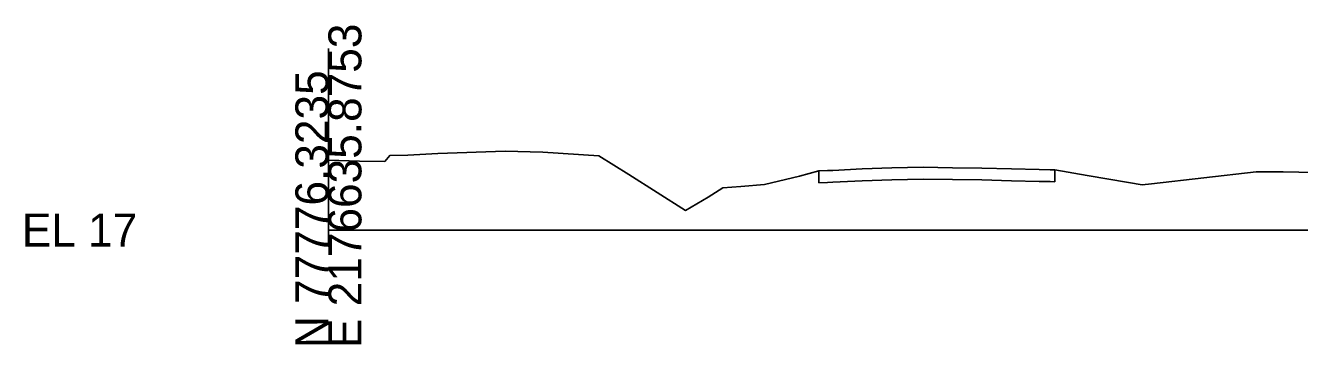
# Model space of a CAD drawing. Extents: x 2177029 to 2201446, y 59897 to 78390.
# Drawn here: x 2200017 to 2200125.1, y 66897.6 to 66924.6 of the extents above; entities that cross this region are included whole.
import ezdxf

# ---------------------------------------------------------------- set-up
doc = ezdxf.new("R2010")
doc.units = 0
for name, color, linetype in [('Exist Cross Section Cell', 7, 'Continuous'), ('Exist XS Ground Line', 7, 'Continuous'), ('Old_Level_3', 7, 'Continuous'), ('Prop CMT Pvmt Wedge Surface 1', 7, 'Continuous'), ('Prop CMT Top Wall Envelope', 7, 'Continuous')]:
    doc.layers.add(name, color=color, linetype=linetype)

msp = doc.modelspace()

# ---------------------------------------------------------------- linework, layer by layer
at = {"layer": 'Exist Cross Section Cell'}
msp.add_line((2200042.73, 66907.31), (2200242.73, 66907.31), dxfattribs=at)
at = {"layer": 'Exist XS Ground Line'}
msp.add_lwpolyline([(2200042.73, 66913.24), (2200045.38, 66913.15), (2200047.51, 66913.12), (2200047.93, 66913.62), (2200049.48, 66913.66), (2200052, 66913.78), (2200057.72, 66913.99), (2200060.92, 66913.9), (2200065.66, 66913.6), (2200068.22, 66912), (2200073.01, 66908.97), (2200074.93, 66910.08), (2200076.19, 66910.87), (2200077.72, 66910.99), (2200079.71, 66911.18), (2200082.67, 66911.87), (2200084.33, 66912.32), (2200085.05, 66912.34), (2200085.51, 66912.36), (2200088.01, 66912.48), (2200090.51, 66912.57), (2200093.18, 66912.63), (2200095.67, 66912.59), (2200098.16, 66912.55), (2200100.66, 66912.49), (2200103.01, 66912.43), (2200103.95, 66912.41), (2200104.34, 66912.4), (2200107.07, 66911.93), (2200110.58, 66911.34), (2200111.75, 66911.14), (2200112.54, 66911.22), (2200121.4, 66912.24), (2200123.7, 66912.23), (2200131.61, 66912.06)], dxfattribs=at)
at = {"layer": 'Old_Level_3'}
msp.add_line((2200042.73, 66905.94), (2200042.73, 66922.68), dxfattribs=at)
at = {"layer": 'Prop CMT Pvmt Wedge Surface 1'}
for p, q in [((2200084.33, 66911.32), (2200084.33, 66912.32)), ((2200090.51, 66911.57), (2200093.18, 66911.63)), ((2200093.18, 66911.63), (2200095.67, 66911.59)), ((2200104.34, 66912.4), (2200104.34, 66911.4)), ((2200084.33, 66911.32), (2200085.05, 66911.34)), ((2200085.05, 66911.34), (2200085.51, 66911.36)), ((2200085.51, 66911.36), (2200088.01, 66911.48)), ((2200088.01, 66911.48), (2200090.51, 66911.57)), ((2200095.67, 66911.59), (2200098.16, 66911.55)), ((2200098.16, 66911.55), (2200100.66, 66911.49)), ((2200100.66, 66911.49), (2200103.01, 66911.43)), ((2200103.01, 66911.43), (2200103.95, 66911.41)), ((2200103.95, 66911.41), (2200104.34, 66911.4))]:
    msp.add_line(p, q, dxfattribs=at)

# ---------------------------------------------------------------- texts
at = {"layer": 'Exist Cross Section Cell'}
for s, p in [('E 2176635.8753', (2200045.53, 66897.31)), ('N 77776.3235', (2200042.73, 66897.31))]:
    msp.add_text(s, height=2.8, rotation=90, dxfattribs=at).set_placement(p)
msp.add_text('EL 17', height=2.8, dxfattribs=at).set_placement((2200016.73, 66905.91))
at = {"layer": 'Prop CMT Top Wall Envelope'}
msp.add_text('-', height=0.0001, dxfattribs=at).set_placement((2200042.73, 66907.31))
msp.add_text('-', height=0.0001, dxfattribs=at).set_placement((2200042.73, 66907.31))

doc.saveas('drawing.dxf')
